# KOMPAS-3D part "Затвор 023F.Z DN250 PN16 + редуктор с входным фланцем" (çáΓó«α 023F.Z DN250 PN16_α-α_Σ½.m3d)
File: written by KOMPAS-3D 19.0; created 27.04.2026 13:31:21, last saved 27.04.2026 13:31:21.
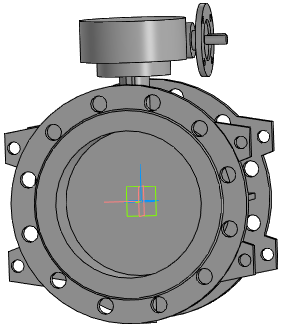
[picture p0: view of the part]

Document properties: Полное имя файла: ..\..\Затвор 023F.Z DN200-DN1600_редуктор с входным фланцем\Затвор 023F.Z DN250 PN16 + редуктор с входным фланцем.a3d

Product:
- Part/product: Затвор 023F.Z DN250 PN16 + редуктор с входным фланцем
    Масса: 77.3054

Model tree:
1. Операция без истории:1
